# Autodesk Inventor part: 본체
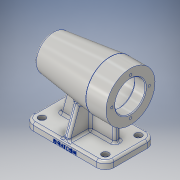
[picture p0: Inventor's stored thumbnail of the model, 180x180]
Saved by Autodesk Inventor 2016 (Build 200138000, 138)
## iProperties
Created: 2018-09
Part Number: 본체
Material: 알루미늄 6061
Document SubType Name: Modeling
Designer: CAMTIC
Density: 2.7 g/cm^3
Appearance: 알루미늄 - 평지
Author: CAMTIC
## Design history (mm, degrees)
sketch "스케치2"
  geometry: L1 (-56, 0)-(56, 0); L2 (56, 0)-(56, 10); L3 (56, 10)-(-56, 10); L4 (-56, 10)-(-56, 0); L5 (0, 12)-(0, -2) reference; L6 (-78.4, 0)-(78.4, 0) reference; L7 (-78.4, 0)-(78.4, 0) reference; L8 (0, -2)-(0, 12) reference; 2 further points
  constraints: 8 end point, 2 parallel, 1 collinear, 1 horizontal, 1 midpoint, 1 perpendicular, 1 point on line
  dimensions: "d0" = 112 distance of L2.end L3.end; "d1" = 10 distance of L1.end L2.end
extrude "돌출1" new body sketch "스케치2" stored distance "d2" = 70; taper "d3" = 0 deg
sketch "스케치3"
  geometry: L1 (56, 74)-(56, 108); L2 (56, 108)-(28.183, 108); L3 (27.818, 107.978)-(-50.331, 98.382); L4 (56, 74)-(-56, 74); L5 (0, 90.525)-(0, -15.088) reference; L6 (-102.597, 0)-(82.433, 0) reference; L7 (-102.597, 0)-(82.433, 0) reference; L8 (0, -15.088)-(0, 90.525) reference; L9 (56, 10)-(-56, 10) reference; A1 r 80 centre (24, 74) between (-52.847, 96.238) and (-56, 74); A2 r 3 centre (-49.965, 95.405) between (-50.331, 98.382) and (-52.847, 96.238); A3 r 3 centre (28.183, 105) between (28.183, 108) and (27.818, 107.978); 4 further points
  constraints: 8 end point, 7 point on circle, 5 point on line, 4 tangent, 3 centre point, 1 horizontal, 1 midpoint, 1 perpendicular, 1 vertical
  dimensions: "d5" = 34 distance between parallel lines of L2 L4; "d6" = 28 distance of L1.end point (28, 108); "d7" = 160 diameter of A1; "d8" = 7 deg angle of L2 L3; "d9" = 112 distance of L1.start L4.end; "d10" = 64 distance between parallel lines of L9 L4; "d43" = 3 radius of A2; "d114" = 3 radius of A3
revolve "회전1" sketch "스케치3" stored, may be unused: angle "d11" = 90 deg
fillet "모깎기1" dims "d48" = 3
fillet "모깎기2" dims "d49" = 12
sketch "스케치4"
  geometry: L1 (56, 40)-(56, 108) reference; L2 (56, 74)-(-50, 74); L3 (-47, 84.5)-(-47, 89.7); L4 (-46.7, 90)-(-43, 90); L5 (-43, 90)-(-43, 91.2); L6 (-42.7, 91.5)-(-25, 91.5); L7 (-25, 91.5)-(-25, 94.7); L8 (-24.7, 95)-(-13, 95); L9 (-13, 95)-(-13, 95); L10 (-10, 98)-(38, 98); L11 (41, 95)-(41, 95); L12 (41, 95)-(56, 95); L13 (-50, 74)-(-50, 81.5); L14 (-47, 84.5)-(-47, 84.5); L15 (56, 95)-(56, 74); A1 r 0.3 centre (-46.7, 89.7) between (-46.7, 90) and (-47, 89.7); A2 r 0.3 centre (-42.7, 91.2) between (-42.7, 91.5) and (-43, 91.2); A3 r 0.3 centre (-24.7, 94.7) between (-24.7, 95) and (-25, 94.7); A4 r 3 centre (-10, 95) between (-10, 98) and (-13, 95); A5 r 3 centre (38, 95) between (41, 95) and (38, 98); A6 r 3 centre (-47, 81.5) between (-47, 84.5) and (-50, 81.5); 2 further points
  constraints: 28 end point, 12 point on circle, 12 tangent, 10 perpendicular, 6 centre point, 5 point on line, 3 equal radius, 1 collinear, 1 horizontal, 1 midpoint, 1 vertical
  dimensions: "d12" = 15 distance between parallel lines of L1 L11; "d13" = 54 distance between parallel lines of L9 L11; "d14" = 12 distance between parallel lines of L7 L9; "d15" = 18 distance from line of L4.end L7; "d16" = 4 distance between parallel lines of L3 L5; "d17" = 3 distance of L3.start point (-50, 84.5); "d18" = 10.5 distance between parallel lines of L2 L14; "d19" = 16 distance between parallel lines of L2 L4; "d20" = 17.5 distance between parallel lines of L2 L6; "d21" = 21 distance between parallel lines of L2 L8; "d22" = 24 distance between parallel lines of L2 L10; "d23" = 0.3 radius of A1; "d24" = 3 radius of A4; "d25" = 3 radius of A6
revolve "회전2" sketch "스케치4" stored, may be unused: angle "d26" = 90 deg
hole "구멍1" diameter "d52" = 5.5; stored, may be unused: countersink angle "d56" = 90 deg, drill point angle "d58" = 118 deg; dims "d50" = 10, "d51" = 10, "d53" = 6, "d54" = 9.5, "d55" = 5.4, "d57" = 8
hole "구멍2" diameter "d61" = 5.5; stored, may be unused: countersink angle "d65" = 90 deg, drill point angle "d67" = 118 deg; dims "d59" = 10, "d60" = 10, "d62" = 6, "d63" = 9.5, "d64" = 5.4, "d66" = 8
sketch "스케치7"
  geometry: L1 (-49, -74)-(49, -74) reference; L2 (0, -95.6)-(0, 55.6) reference; L3 (0, -95.6)-(0, 55.6) reference; L4 (49, -74)-(-49, -74) reference; C1 r 21 at (0, 0) reference; 2 further points
  constraints: 1 point on line
  dimensions: "d68" = 26 distance of C1.centre point (0, 26)
hole "구멍3" sketch "스케치7" at (0, 26) diameter "d69" = 3.242; stored, may be unused: countersink angle "d73" = 90 deg, drill point angle "d75" = 118 deg; dims "d70" = 8, "d71" = 9.5, "d72" = 5.4, "d74" = 11
chamfer "모따기2" distance "d79" = 1; stored, may be unused: second distance "d80" = 2, angle "d81" = 45 deg
sketch "스케치8"
  geometry: L1 (88, 67)-(0, 67) reference; L2 (100, 55)-(100, 9) reference; L3 (0, -3)-(88, -3) reference; L4 (-12, 55)-(-12, 9) reference; L5 (44, 84.479)-(44, -20.479) reference; L6 (125.879, 32)-(-37.879, 32) reference; L7 (-37.879, 32)-(125.879, 32) reference; L8 (44, 84.479)-(44, -20.479) reference; L9 (6, 36)-(82, 36); L10 (82, 36)-(82, 28); L11 (82, 28)-(6, 28); L12 (6, 28)-(6, 36); L13 (40, 67)-(48, 67); L14 (48, 67)-(48, -3); L15 (48, -3)-(40, -3); L16 (40, -3)-(40, 67); C1 r 2.75 at (0, 9) reference; C2 r 2.75 at (0, 55) reference; C3 r 2.75 at (88, 55) reference; C4 r 2.75 at (88, 9) reference; A1 r 12 centre (0, 55) between (0, 67) and (-12, 55) reference; A2 r 12 centre (88, 55) between (100, 55) and (88, 67) reference; A3 r 12 centre (88, 9) between (88, -3) and (100, 9) reference; A4 r 12 centre (0, 9) between (-12, 9) and (0, -3) reference; 3 further points
  constraints: 16 end point, 4 parallel, 2 collinear, 2 horizontal, 2 midpoint, 2 perpendicular, 2 point on line
  dimensions: "d91" = 18 distance between parallel lines of L4 L12; "d92" = 18 distance between parallel lines of L2 L10; "d93" = 8 distance between parallel lines of L16 L14; "d94" = 8 distance between parallel lines of L11 L9
extrude "돌출4" join sketch "스케치8" distance "d89" = 40; taper "d90" = 0 deg
feature "면 기울기3" dims angle "d95" = 20 deg
feature "면 기울기4" dims angle "d96" = 15 deg
fillet "모깎기3" dims "d97" = 3
fillet "모깎기4" dims "d98" = 3
fillet "모깎기5" dims "d99" = 3
fillet "모깎기6" dims "d100" = 3
fillet "모깎기7" dims "d101" = 3
fillet "모깎기8" dims "d102" = 3
fillet "모깎기9" dims "d103" = 3
fillet "모깎기10" dims "d104" = 3
fillet "모깎기11" dims "d105" = 3
fillet "모깎기12" dims "d106" = 3
fillet "모깎기13" dims "d107" = 3
sketch "스케치9"
  geometry: L1 (-5.899, 4.74)-(5.899, 4.74); L2 (5.899, 4.74)-(5.899, 1.26); L3 (5.899, 1.26)-(-5.899, 1.26); L4 (-5.899, 1.26)-(-5.899, 4.74); L5 (-44, 0)-(44, 0) reference; L6 (56, 0)-(56, 7) reference; 3 further points
  constraints: 2 midpoint, 2 other
  dimensions: "d108" = 3 distance from line of L5 point (5.899, 3); "d110" = 56 distance from line of L6 point (0, 4.74)
feature "엠보싱1" sketch "스케치9" dims "d0" = 112, "d1" = 10, "d5" = 34, "d6" = 28, "d7" = 160, "d8" = 7 deg, "d9" = 112, "d10" = 64, "d43" = 3, "d111" = 0.5, "d112" = 0, "d114" = 3
node "솔리드1"
mirror "대칭1"
pattern_circular "원형 패턴1" dims angle "d77" = 360 deg
node "투영된 루프1"
other parameters: "d30" = 8, "d31" = 8, "d37" = 8, "d38" = 8
